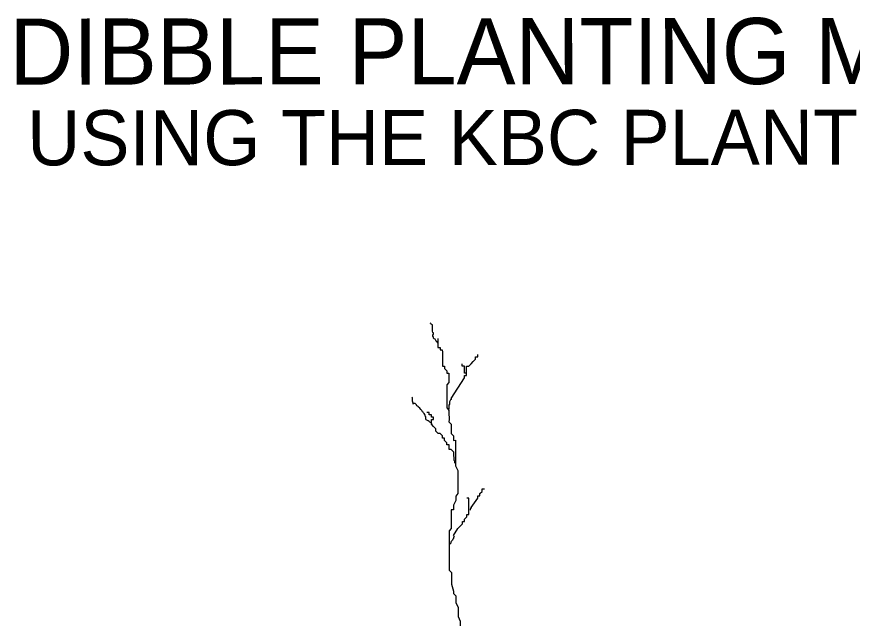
# Model space of a CAD drawing. Extents: x 816132 to 817815, y 885694 to 886789.
# Drawn here: x 816717.8 to 816863.1, y 886459.9 to 886565.5 of the extents above; entities that cross this region are included whole.
import ezdxf

# ---------------------------------------------------------------- set-up
doc = ezdxf.new("R2010")
doc.units = 0
doc.layers.add('Silt Fence Coir Fiber Wattle Break Detail CELL', color=7, linetype='Continuous')

msp = doc.modelspace()

# ---------------------------------------------------------------- linework, layer by layer
at = {"layer": 'Silt Fence Coir Fiber Wattle Break Detail CELL'}
for points in [[(816791.03, 886508.83), (816790.83, 886509.07), (816790.73, 886509.17), (816790.64, 886509.28), (816790.54, 886509.48), (816790.35, 886509.58), (816790.25, 886509.68), (816790.25, 886509.88), (816790.16, 886509.98), (816790.16, 886510.18), (816790.25, 886510.38), (816790.25, 886510.58), (816790.16, 886510.68), (816790.06, 886510.89), (816790.06, 886511.19), (816790.06, 886511.39), (816790.06, 886511.59), (816790.06, 886511.79), (816790.06, 886511.99), (816789.87, 886512.09), (816789.77, 886512.2), (816789.67, 886512.3)], [(816791.03, 886509.63), (816791.03, 886508.83), (816791.03, 886508.43), (816791.03, 886508.02), (816791.41, 886508.02), (816791.41, 886507.62), (816791.79, 886507.62), (816791.8, 886507.22), (816791.8, 886506.81), (816791.8, 886506.41), (816791.8, 886506.01), (816791.8, 886505.61), (816791.8, 886505.2), (816791.8, 886504.8), (816792.18, 886504.8), (816792.18, 886504.4), (816792.57, 886503.99), (816792.57, 886503.59), (816792.95, 886503.59), (816792.95, 886503.19), (816792.95, 886502.79), (816792.95, 886502.38), (816792.95, 886501.98), (816792.57, 886501.58), (816792.57, 886501.17), (816792.57, 886500.77), (816792.57, 886500.37), (816792.57, 886499.97), (816792.57, 886499.56), (816792.57, 886499.16), (816792.57, 886498.76), (816792.57, 886498.35), (816792.57, 886497.95), (816792.57, 886497.55), (816792.95, 886497.14), (816792.95, 886496.74), (816792.95, 886496.34), (816792.96, 886495.93), (816792.96, 886495.53), (816792.95, 886495.13), (816793.34, 886494.73), (816793.34, 886494.32), (816793.34, 886493.92), (816793.34, 886493.52), (816793.34, 886493.11), (816793.73, 886492.71), (816793.73, 886491.9), (816794.11, 886491.91), (816794.11, 886491.5), (816794.11, 886491.1), (816794.11, 886490.7), (816794.11, 886490.29), (816794.11, 886489.49), (816794.11, 886488.68), (816794.11, 886487.47), (816794.5, 886486.67), (816794.5, 886486.26), (816794.5, 886485.86), (816794.5, 886485.46), (816794.5, 886485.05), (816794.5, 886484.65), (816794.5, 886484.25), (816794.5, 886483.85), (816794.5, 886483.44), (816794.5, 886483.04), (816794.5, 886482.64), (816794.12, 886482.23), (816794.12, 886481.43), (816793.73, 886480.62), (816793.74, 886480.22), (816793.73, 886479.82), (816793.35, 886479.82), (816793.35, 886479.41), (816793.35, 886479.01), (816793.35, 886478.61), (816793.35, 886478.2), (816793.35, 886477.8), (816793.35, 886477.4), (816793.35, 886476.99), (816793.35, 886476.59), (816792.97, 886476.19), (816792.97, 886475.78), (816792.97, 886475.38), (816792.97, 886474.98), (816792.97, 886474.58), (816792.97, 886474.17), (816792.97, 886473.77), (816792.97, 886473.37), (816792.97, 886472.96), (816792.97, 886472.16), (816792.97, 886471.75), (816792.97, 886471.35), (816792.97, 886470.54), (816792.97, 886470.14), (816792.97, 886469.74), (816792.97, 886469.34), (816793.36, 886468.93), (816793.36, 886468.53), (816793.36, 886468.13), (816793.36, 886467.72), (816793.36, 886466.92)], [(816796.02, 886503.19), (816796.02, 886504.4), (816796.02, 886504.8), (816796.4, 886504.8), (816796.79, 886505.21), (816797.17, 886505.61), (816797.56, 886506.01), (816797.56, 886506.42), (816797.94, 886506.42), (816797.94, 886506.82)], [(816793.34, 886499.16), (816795.64, 886502.79), (816795.64, 886503.19), (816796.02, 886503.19), (816796.02, 886503.59), (816795.64, 886503.59), (816795.64, 886504), (816795.64, 886504.4), (816795.64, 886504.8), (816795.25, 886504.8), (816795.25, 886505.2)], [(816789.88, 886494.72), (816789.98, 886494.87), (816789.59, 886495.07), (816789.5, 886495.17), (816789.3, 886495.27), (816789.21, 886495.37), (816789.01, 886495.47), (816788.92, 886495.57), (816788.92, 886495.77), (816788.92, 886495.97), (816788.82, 886496.08), (816788.82, 886496.28), (816788.73, 886496.38), (816788.63, 886496.58), (816788.53, 886496.68), (816788.44, 886496.78), (816788.34, 886496.88), (816788.25, 886497.08), (816788.05, 886497.28), (816787.86, 886497.48), (816787.67, 886497.69), (816787.57, 886497.79), (816787.38, 886497.89), (816787.28, 886498.09), (816787.19, 886498.19), (816787.09, 886498.29), (816786.8, 886498.29), (816786.71, 886498.19), (816786.71, 886498.39), (816786.61, 886498.69), (816786.61, 886498.89), (816786.61, 886499.1), (816786.61, 886499.3), (816786.52, 886499.4)], [(816793.34, 886499.16), (816793.34, 886499.02), (816793.24, 886498.92), (816793.14, 886498.82), (816793.05, 886498.62), (816793.05, 886498.41), (816793.05, 886498.21), (816792.95, 886498.01), (816792.95, 886497.81), (816792.95, 886497.61), (816792.95, 886497.41), (816792.86, 886497.31), (816792.86, 886497.1)], [(816793.73, 886489.89), (816793.34, 886490.29), (816792.96, 886490.29), (816792.96, 886490.69), (816792.96, 886491.1), (816792.57, 886491.1), (816792.57, 886491.5), (816792.19, 886491.9), (816792.19, 886492.31), (816791.81, 886492.31), (816791.81, 886492.71), (816791.42, 886493.11), (816791.04, 886493.11), (816790.65, 886493.52), (816790.65, 886493.92), (816790.27, 886494.32), (816789.88, 886494.72), (816789.88, 886495.13), (816789.88, 886495.53), (816790.27, 886495.53), (816790.27, 886495.93), (816789.88, 886495.93), (816789.88, 886496.34), (816789.5, 886496.34), (816789.5, 886496.74), (816789.11, 886496.74)], [(816793.73, 886489.89), (816793.73, 886489.35), (816793.73, 886489.15), (816793.82, 886489.05), (816793.82, 886488.84), (816793.82, 886488.64), (816793.82, 886488.44), (816793.92, 886488.34), (816793.92, 886488.14), (816793.92, 886487.94)], [(816796.81, 886480.22), (816797.96, 886481.83), (816797.96, 886482.24), (816798.34, 886482.24), (816798.34, 886482.64), (816798.72, 886483.04), (816798.72, 886483.45), (816799.11, 886483.45)], [(816793.74, 886475.38), (816794.51, 886476.59), (816794.89, 886477), (816795.27, 886477.4), (816795.27, 886477.8), (816795.66, 886477.8), (816795.66, 886478.21), (816796.04, 886478.61), (816796.04, 886479.01), (816796.42, 886479.01), (816796.42, 886479.41), (816796.42, 886479.82), (816796.42, 886480.22), (816796.42, 886480.62), (816796.42, 886481.03), (816796.42, 886481.43), (816796.42, 886481.83), (816796.04, 886481.83)], [(816796.81, 886480.22), (816796.7, 886480.06), (816796.61, 886479.96), (816796.61, 886479.76)], [(816793.74, 886475.38), (816793.83, 886475.14), (816793.74, 886475.04), (816793.74, 886474.84), (816793.64, 886474.74), (816793.55, 886474.54), (816793.45, 886474.44), (816793.35, 886474.34), (816793.26, 886474.23), (816793.26, 886474.03), (816793.16, 886473.93), (816793.07, 886473.83)], [(816793.36, 886466.92), (816793.75, 886465.71), (816793.75, 886465.31), (816794.13, 886464.9), (816794.13, 886464.1), (816794.13, 886463.69), (816794.52, 886462.89), (816794.52, 886462.49), (816794.52, 886461.68), (816794.52, 886461.28), (816794.9, 886460.47), (816794.9, 886459.67)]]:
    msp.add_lwpolyline(points, dxfattribs=at)

# ---------------------------------------------------------------- texts
for s, height, p in [('DIBBLE PLANTING METHOD', 11.4927, (816716.54, 886553.73)), ('USING THE KBC PLANTING BAR', 9.5773, (816719.61, 886539.7))]:
    msp.add_text(s, height=height, rotation=0.045, dxfattribs=at).set_placement(p)

doc.saveas('drawing.dxf')
